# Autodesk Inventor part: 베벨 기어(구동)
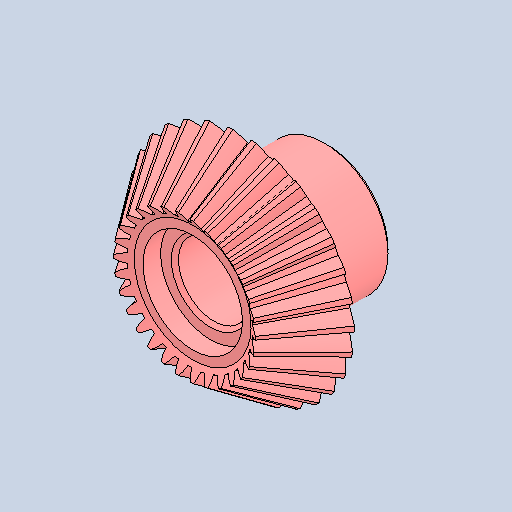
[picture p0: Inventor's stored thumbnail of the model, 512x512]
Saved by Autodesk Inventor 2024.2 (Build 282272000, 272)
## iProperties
Created: 2026-01
Part Number: 베벨 기어(구동)
Material: 강철, 합금
Document SubType Name: Modeling
Designer: home
Density: 7.73 g/cm^3
Appearance: 기본값
Author: jhkim
Sending System: Autodesk Inventor 2026
Preprocessor: ST-DEVELOPER v20.1
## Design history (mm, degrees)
feature "Solid1"
node "솔리드1"
